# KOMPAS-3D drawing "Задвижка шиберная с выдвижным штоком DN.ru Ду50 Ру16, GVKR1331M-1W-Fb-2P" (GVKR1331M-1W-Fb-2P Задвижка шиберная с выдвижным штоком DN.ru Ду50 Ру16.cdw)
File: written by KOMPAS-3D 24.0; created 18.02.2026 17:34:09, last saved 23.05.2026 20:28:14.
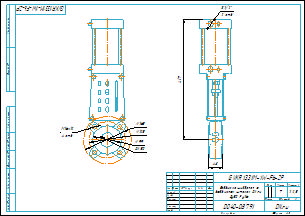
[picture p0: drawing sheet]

Document properties: Автор: R2D2; Форматы листов документа: A3; Полное имя файла: GVKR1331M-1W-Fb-2P Задвижка шиберная с выдвижным штоком DN.ru Ду50 Ру16.m3d; Масса: 7; Наименование: Задвижка шиберная с выдвижным штоком DN.ru Ду50 Ру16; Количество листов документа: 1; Примечание: D040-08791

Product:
- Part/product: Задвижка шиберная с выдвижным штоком DN.ru Ду50 Ру16  | designation GVKR1331M-1W-Fb-2P
    Масса: 7
    Раздел спецификации: Прочие изделия
    Примечание: D040-08791

Referenced files in E:\Работа\Зайцев\Для компаса\: чертеж DN.ru А3.cdt
Referenced files in E:\Работа\Зайцев\GVKR1331M-1W-Fb-2P Задвижка шиберная с выдвижным штоком DN.ru Ду50-300 Ру16-10-6 с пневмоприводом\исходные материалы\DN50\DN50\: GVKR1331M-1W-Fb-2P Задвижка шиберная с выдвижным штоком DN.ru Ду50 Ру16.m3d
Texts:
  чертеж DN.ru А3.cdt
  Задвижка шиберная с
  выдвижным штоком DN.ru
  Ду50 Ру16
  GVKR1331M-1W-Fb-2P
  Задвижка шиберная с выдвижным штоком DN.ru Ду50 Ру16
  GVKR1331M-1W-Fb-2P Задвижка шиберная с выдвижным штоком DN.ru Ду50 Ру16
Dimensions and other numbers on the sheet: 1:2,5; 0; 1; 2; 7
